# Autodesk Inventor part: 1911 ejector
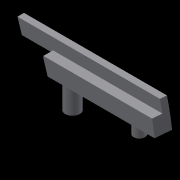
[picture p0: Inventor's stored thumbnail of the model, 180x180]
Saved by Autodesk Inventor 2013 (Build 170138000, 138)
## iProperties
Created: 2013-02
Part Number: 1911 ejector
Material: Generic
Document SubType Name: Modeling
Designer: John
Density: 1 g/cm^3
Author: John
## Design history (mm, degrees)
sketch "Sketch1"
  geometry: L1 (23.371, 5.918)-(0.906, 5.918); L2 (0, 3.429)-(0.906, 5.918) reference; L3 (0, 3.429)-(0, 2.921) reference; L4 (0, 2.921)-(0.921, 0) reference; L5 (4.572, 5.918)-(23.371, 5.918); L6 (0.921, 0)-(24.486, 0); A1 r 46.05 centre (-21.229, -5.547) between (24.486, 0) and (23.371, 5.918); 1 further point
  constraints: 12 end point, 2 point on circle, 1 centre point, 1 parallel, 1 point on line, 1 vertical, 2 other
  dimensions: "d32" = 92.1004 diameter of A1
extrude "Extrusion3" new body sketch "Sketch1" distance "d13" = 1.4224; taper "d14" = 0 deg
sketch "Sketch8"
  geometry: L1 (0, 3.429)-(0, 2.921) reference; L2 (0, 2.921)-(0.921, 0) reference; L3 (0.921, 0)-(24.486, 0) reference; L4 (23.371, 5.918)-(0.906, 5.918) reference; L5 (0, 3.429)-(23.938, 3.429); A1 r 46.05 centre (-21.229, -5.547) between (24.486, 0) and (23.371, 5.918) reference; 1 further point
  constraints: 2 end point, 1 parallel, 1 point on circle
extrude "Extrusion7" join sketch "Sketch8" distance "d33" = 2.0828; taper "d34" = 0 deg
sketch "Sketch9"
  geometry: L1 (-0.921, 0)-(-0.921, 3.505) reference; C1 r 1.581 at (3.651, 1.753); C2 r 1.226 at (18.51, 2.083)
  constraints: 2 centre point
  dimensions: "d36" = 3.1623 diameter of C1; "d39" = 2.4511 diameter of C2
extrude "Extrusion8" join sketch "Sketch9" distance "d40" = 2.286; taper "d41" = 0 deg
sketch "Sketch10"
  geometry: C1 r 1.581 at (0, 0) reference; 1 further point
extrude "Extrusion9" join sketch "Sketch10" distance "d42" = 3.048; taper "d43" = 0 deg
sketch "Sketch12"
  geometry: L1 (23.565, 0)-(23.565, 3.505) reference; L2 (0, 3.505)-(23.565, 3.505) reference; L3 (23.565, 0)-(23.258, 3.505); L4 (23.565, 0)-(27.083, 0); 1 further point
  constraints: 4 end point, 1 equal length, 1 horizontal, 1 point on line
  dimensions: "d44" = 95 deg angle of L4 L3
sketch "Sketch13"
  geometry: A1 r 46.05 centre (21.229, -5.547) between (-23.371, 5.918) and (-24.486, 0) reference; A2 r 46.05 centre (21.229, -5.547) between (-22.28, 9.537) and (-24.821, -5.547); 1 further point
  constraints: 3 point on circle, 1 centre point, 1 coincident
sweep "Sweep2" sketch "Sketch12", "Sketch13" dims "d45" = 0
sketch "Sketch14"
  geometry: L1 (-0.906, 5.918)-(0, 3.429) reference; L2 (0, 2.921)-(-0.921, 0) reference; L3 (0, 3.429)-(0, 2.921) reference; L4 (-0.906, 5.918)-(7.724, 5.918); L5 (0, 2.921)-(6.779, 2.921); L6 (7.724, 5.918)-(6.779, 2.921); 1 further point
  constraints: 6 end point, 2 parallel, 1 perpendicular
extrude "Extrusion10" join sketch "Sketch14" stored distance "d46" = 25.4; taper "d47" = 0 deg
body "Solid2"
